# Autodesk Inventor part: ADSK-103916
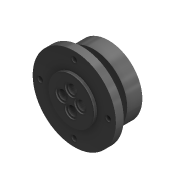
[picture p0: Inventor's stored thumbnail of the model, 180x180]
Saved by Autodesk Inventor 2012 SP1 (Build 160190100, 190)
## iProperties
Shininess: 0.0
Created: 2001-01
Part Number: ADSK-103916
Document SubType Name: Modeling
Stock Number: ADSK-103916
Density: 1 g/cm^3
Material: Default
Density: 0.0
Volumn: 0.0
Area: 0.0
PropertySet Name: Model Information
Control State: 0
Master: False
Checked Out: False
Author: gao
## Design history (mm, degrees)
node "Extrusion1" dims "d1" = 20.03, "d2" = 0
  sketch "Sketch1"
    geometry: C1 r 44.45 at (-0.78, 0)
    constraints: 1 centre point
    dimensions: "d0" = 88.9 diameter of C1
node "Extrusion2" dims "d4" = 15.0876, "d5" = 0
  sketch "Sketch2"
    geometry: C1 r 44.45 at (0, 0) reference; C2 r 25.4 at (0, 0)
    constraints: 1 centre point, 1 coincident
    dimensions: "d3" = 50.8 diameter of C2
node "Extrusion3" dims "d7" = 10.3124, "d8" = 0
  sketch "Sketch3"
    geometry: C1 r 25.4 at (0, 0) reference; C2 r 54.966 at (0, 0)
    constraints: 1 centre point, 1 coincident
    dimensions: "d6" = 109.9312 diameter of C2
node "Extrusion4" dims "d10" = 3.96875, "d11" = 0
  sketch "Sketch4"
    geometry: C1 r 54.966 at (0, 0) reference; C2 r 29.997 at (0, 0)
    constraints: 1 centre point, 1 coincident
    dimensions: "d9" = 59.9948 diameter of C2
node "Hole1" dims "d13" = 7.14375, "d14" = 9.525, "d15" = 6.35, "d16" = 60 deg, "d17" = 19.05, "d18" = 118 deg
  sketch "Sketch5" dims "d12" = 89.9922
    geometry: C1 r 54.966 at (0, 0) reference; 2 further points
    constraints: 1 coincident, 1 vertical alignment, 2 other
node "Circular Pattern1" dims "d19" = 40, "d21" = 90 deg
node "Hole2" dims "d23" = 16.764, "d24" = 9.525, "d25" = 6.35, "d26" = 60 deg, "d27" = 1.524, "d28" = 0
  sketch "Sketch6" dims "d22" = 24.60625
    geometry: C1 r 29.997 at (0, 0) reference; 2 further points
    constraints: 1 coincident, 1 vertical alignment, 2 other
node "Hole3" dims "d29" = 12.0396, "d30" = 9.525, "d31" = 6.35, "d32" = 60 deg, "d33" = 11.176, "d34" = 0
  sketch "Sketch7"
    geometry: C1 r 8.382 at (0, 0) reference; 1 further point
    constraints: 1 coincident
node "Circular Pattern2" dims "d35" = 40, "d37" = 90 deg
body "Solid1"
